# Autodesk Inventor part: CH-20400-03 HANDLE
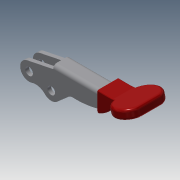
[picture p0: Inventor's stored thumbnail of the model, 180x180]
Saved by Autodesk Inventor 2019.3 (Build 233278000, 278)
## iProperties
Created: 2012-09
Part Number: CH-20400-03 HANDLE
Material: Ogólny
Document SubType Name: Modeling
Designer: CADENGINEERING4
Density: 1 g/cm^3
Appearance: Domyślna
Author: CADENGINEERING4
Revision Number: ÈÎºÎ
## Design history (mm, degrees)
feature "NONE"
feature "À­Éì25"
feature "À­Éì30"
node "Bryła1"
node "Bryła2"
node "Bryła3"
